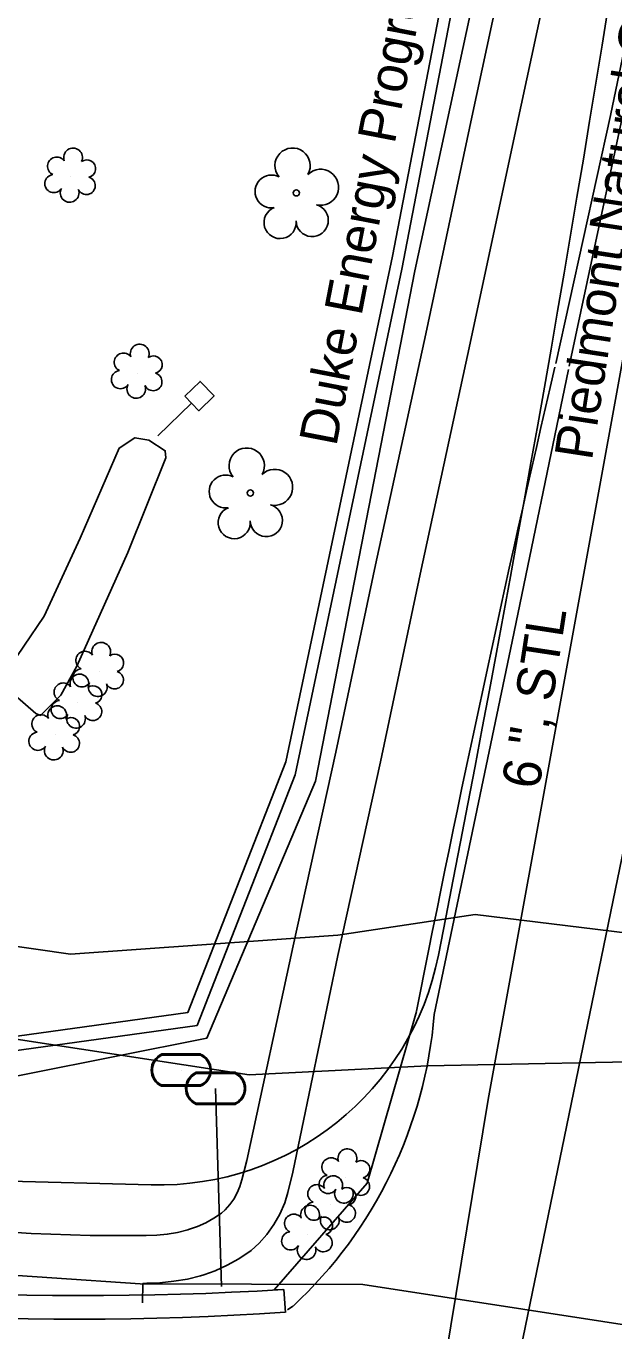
# Model space of a CAD drawing. Extents: x 1614427 to 1617186, y 896524 to 905462.
# Drawn here: x 1616565.9 to 1616627.8, y 901675.1 to 901812.5 of the extents above; entities that cross this region are included whole.
import ezdxf

# ---------------------------------------------------------------- set-up
doc = ezdxf.new("R2010")
doc.units = 0
for name, color, linetype in [('Exist Building', 7, 'Continuous'), ('Exist Right of Way Line', 7, 'Continuous'), ('Exist Roads Curbs', 7, 'Continuous'), ('Exist Roads EOP', 7, 'Continuous'), ('Exist Roads EOP Other', 7, 'Continuous'), ('Exist Roads EOT', 7, 'Continuous'), ('Exist Utilities Gas UG Line SUE LOS B', 7, 'Continuous'), ('Exist Utilities Gas UG Line SUE LOS B Text', 7, 'Continuous'), ('Exist Utilities Power UG Cable SUE LOS B', 7, 'Continuous'), ('Exist Utilities Power UG Cable SUE LOS B Text', 7, 'Continuous'), ('Exist Utilities Telephone UG Cable SUE LOS B', 7, 'Continuous'), ('Exist Utilities Telephone UG FO SUE LOS B', 7, 'Continuous'), ('Exist Utilities TV UG FO Cable SUE LOS B', 7, 'Continuous'), ('Exist Utilities Water Meter CELL', 7, 'Continuous'), ('Exist Utilities Water UG Line SUE LOS B', 7, 'Continuous'), ('Exist Vegetation Hedge Row', 7, 'Continuous'), ('Exist Vegetation Shrub CELL', 7, 'Continuous'), ('Exist Vegetation Tree CELL', 7, 'Continuous')]:
    doc.layers.add(name, color=color, linetype=linetype)

# ---------------------------------------------------------------- blocks, each defined once
blk = doc.blocks.new('EXIST UTILITIES WATER METER')
at = {"layer": 'Exist Utilities Water Meter CELL'}
blk.add_line((0, 0), (0, 0), dxfattribs=at)
for points in [[(-0.0408, 0.034), (0.0408, 0.034)], [(-0.0408, 0.0312), (0.0408, 0.0312)], [(0.0408, -0.0312), (-0.0413, -0.0312)], [(0.0408, -0.034), (-0.0413, -0.034)]]:
    blk.add_lwpolyline(points, dxfattribs=at)
for centre, radius, start, end in [((-0.0261, -0.0001), 0.0371, 113.178, 245.9794), ((-0.0259, -0.0001), 0.0347, 115.3009, 243.7824), ((0.0259, 0), 0.0371, 293.6483, 66.3084), ((0.0261, 0), 0.0345, 295.1272, 64.8728)]:
    blk.add_arc(centre, radius, start, end, dxfattribs=at)

msp = doc.modelspace()

# ---------------------------------------------------------------- linework, layer by layer
at = {"layer": 'Exist Building'}
msp.add_lwpolyline([(1616582.61, 901773.54), (1616584.21, 901775.1), (1616585.69, 901773.57), (1616584.09, 901772.01)], close=True, dxfattribs=at)
msp.add_lwpolyline([(1616579.75, 901769.36), (1616583.32, 901772.8)], dxfattribs=at)
at = {"layer": 'Exist Right of Way Line'}
msp.add_line((1616553.32, 901691.18), (1616579.08, 901690.51), dxfattribs=at)
for centre, radius, start, end in [((1613828.3, 902264.36), 2834.79, 348.81938, 354.06667), ((1616579.86, 901720.5), 30, 268.5167, 348.8194)]:
    msp.add_arc(centre, radius, start, end, dxfattribs=at)
at = {"layer": 'Exist Roads Curbs'}
msp.add_ellipse((1616573.1, 902027.68), major_axis=(332.83, 110.98), ratio=0.993612, start_param=4.203204, end_param=4.448986, dxfattribs=at)
msp.add_spline([(1616576.44, 901651.14), (1616560.36, 901651.87), (1616541.57, 901653.2), (1616514.26, 901656.47), (1616480.87, 901662.8), (1616452.55, 901670.88), (1616427.97, 901679.5)], degree=3, dxfattribs=at)
at = {"layer": 'Exist Roads EOP'}
for p, q in [((1616601.81, 901690.68), (1616606.99, 901708.78)), ((1616592.01, 901679.45), (1616601.81, 901690.68)), ((1616593.04, 901679.48), (1616592.01, 901679.45)), ((1616593.19, 901677.09), (1616593.04, 901679.48))]:
    msp.add_line(p, q, dxfattribs=at)
msp.add_lwpolyline([(1616621.64, 901776.98), (1616627.39, 901803.1), (1616632.77, 901828.92), (1616641.71, 901868.37), (1616650.08, 901907.37), (1616655.28, 901931.6)], dxfattribs=at)
for centre, major_axis, ratio, start_param, end_param in [((1618623.91, 901315), (-543.78, -2018.83), 0.982805, 4.748311, 4.78148), ((1616571.82, 902020.2), (313.25, 144.66), 0.995767, 4.092093, 4.343375)]:
    msp.add_ellipse(centre, major_axis=major_axis, ratio=ratio, start_param=start_param, end_param=end_param, dxfattribs=at)
msp.add_spline([(1616600.7, 901615.07), (1616596.49, 901640.71), (1616577.82, 901651.88), (1616577.76, 901653.58), (1616560.38, 901654.4), (1616541.66, 901655.74), (1616514.62, 901658.97), (1616481.57, 901665.46), (1616453.29, 901673.28), (1616429.01, 901681.85), (1616427.56, 901682.36), (1616413.54, 901687.44), (1616400.43, 901690.54), (1616382.85, 901691.64), (1616359.81, 901688.16), (1616349.76, 901685.26), (1616334.54, 901681.3), (1616320.23, 901678.77)], degree=3, dxfattribs=at)
at = {"layer": 'Exist Roads EOP Other'}
for points in [[(1616558.2, 901685.95), (1616566.42, 901685.4), (1616572.64, 901685.18), (1616578.48, 901685.18), (1616578.55, 901685.17), (1616579.66, 901685.21), (1616580.76, 901685.31), (1616581.84, 901685.5), (1616582.91, 901685.77), (1616583.01, 901685.8), (1616583.93, 901686.12), (1616584.81, 901686.52), (1616585.66, 901686.99), (1616586.46, 901687.53), (1616586.84, 901687.88), (1616587.33, 901688.43), (1616587.76, 901689.02), (1616588.12, 901689.66), (1616588.4, 901690.33), (1616588.62, 901691.03), (1616589.13, 901693.08), (1616594.02, 901715.68), (1616598.5, 901736.07), (1616602.69, 901755.79), (1616607.96, 901780.12), (1616612.82, 901802.9), (1616617.67, 901825.43)], [(1616578.16, 901678.11), (1616578.19, 901680.14), (1616578.61, 901680.17), (1616579.99, 901680.21), (1616581.44, 901680.36), (1616582.88, 901680.6), (1616584.26, 901680.95), (1616584.6, 901681.05), (1616585.81, 901681.48), (1616587.07, 901682.05), (1616588.28, 901682.73), (1616589.58, 901683.6), (1616590.42, 901684.37), (1616591.24, 901685.29), (1616591.99, 901686.33), (1616592.62, 901687.44), (1616593.12, 901688.62), (1616593.45, 901689.7), (1616593.99, 901691.86), (1616598.71, 901714.66), (1616603.19, 901735.05), (1616607.38, 901754.79), (1616612.65, 901779.11), (1616617.51, 901801.89), (1616622.36, 901824.42)]]:
    msp.add_lwpolyline(points, dxfattribs=at)
at = {"layer": 'Exist Roads EOT'}
msp.add_line((1616593.41, 901677.36), (1616593.99, 901677.75), dxfattribs=at)
for points in [[(1616623.04, 901776.71), (1616628.63, 901802.84), (1616634.16, 901828.59), (1616642.69, 901868.2), (1616651.43, 901907.18), (1616657.03, 901931.53)], [(1616608.85, 901708.44), (1616617.05, 901747.7), (1616622.98, 901776.36)]]:
    msp.add_lwpolyline(points, dxfattribs=at)
msp.add_ellipse((1616561.86, 901712.27), major_axis=(4.78, 46.93), ratio=0.999551, start_param=3.993091, end_param=4.732604, dxfattribs=at)
at = {"layer": 'Exist Utilities Gas UG Line SUE LOS B'}
msp.add_lwpolyline([(1616538.79, 901324.29), (1616552.84, 901386.17), (1616571.68, 901471.14), (1616584.04, 901531.54), (1616593.62, 901586.74), (1616603.9, 901635.05), (1616614.54, 901699.5), (1616631.36, 901792.12), (1616640.8, 901853.71), (1616647.39, 901906.62), (1616655.55, 901983.89), (1616661.01, 902037.25)], dxfattribs=at)
at = {"layer": 'Exist Utilities Power UG Cable SUE LOS B'}
for points in [[(1616454.2, 901982.47), (1616452.09, 901959.01), (1616448.15, 901937.94), (1616436.91, 901904.44), (1616414.57, 901852.23), (1616406.71, 901821.07), (1616409.3, 901784.96), (1616413.11, 901774.57), (1616426.11, 901752.3), (1616435.59, 901746.32), (1616447.34, 901733.78), (1616483.5, 901710.48), (1616530.04, 901703.19), (1616556.28, 901703.48), (1616583.9, 901707.29), (1616594.22, 901733.69), (1616605.43, 901786.91), (1616617.42, 901849.02), (1616627.72, 901895.28)], [(1616521.47, 901705.75), (1616529.07, 901704.56), (1616555.31, 901704.85), (1616582.92, 901708.65), (1616593.24, 901735.06), (1616604.45, 901788.28), (1616616.44, 901850.39), (1616626.74, 901896.65)], [(1616321.85, 901655.54), (1616340.38, 901656.93), (1616355.03, 901659.84), (1616371, 901660.64), (1616397.99, 901656.61), (1616411.28, 901688.81), (1616423.43, 901725.11), (1616429.1, 901738.02), (1616434.18, 901742.07), (1616436.04, 901741.86), (1616447.03, 901732.28), (1616483, 901709.43), (1616531.15, 901699.01), (1616556.38, 901700.28), (1616584.94, 901705.97), (1616596.35, 901733.02), (1616606.82, 901786.74), (1616620.07, 901848.21), (1616628.54, 901895.32)]]:
    msp.add_lwpolyline(points, dxfattribs=at)
at = {"layer": 'Exist Utilities Telephone UG Cable SUE LOS B'}
msp.add_lwpolyline([(1616586.65, 901614.7), (1616592.7, 901627.45), (1616597.67, 901647), (1616601.16, 901647.82), (1616608.45, 901646.9), (1616613.6, 901651.99), (1616633.98, 901750.98), (1616649.47, 901834.39), (1616660.58, 901920.16), (1616668.64, 902000.09), (1616671.96, 902044.94), (1616671.51, 902046.39), (1616670.53, 902047.17), (1616656.18, 902049.88), (1616655.65, 902049.04), (1616655.13, 902049.4), (1616655.43, 902048.87), (1616655.12, 902049.21)], dxfattribs=at)
at = {"layer": 'Exist Utilities Telephone UG FO SUE LOS B'}
msp.add_lwpolyline([(1616403.03, 901799.89), (1616405.04, 901786.96), (1616407.42, 901779.6), (1616413.72, 901777.14), (1616420.34, 901772.02), (1616441.69, 901749.86), (1616460.62, 901734.03), (1616479.89, 901715.6), (1616485.43, 901711.46), (1616493.52, 901710.05), (1616500.25, 901708.45), (1616507.39, 901707.17), (1616536.69, 901701.35), (1616564.86, 901705.85), (1616589.38, 901702.1), (1616608.14, 901703.05), (1616664.78, 901704.15), (1616671.11, 901705.31), (1616671.11, 901705.31), (1616675.41, 901706.02)], dxfattribs=at)
at = {"layer": 'Exist Utilities TV UG FO Cable SUE LOS B'}
msp.add_lwpolyline([(1616479.03, 901712.88), (1616493.29, 901712.8), (1616511.94, 901716.14), (1616527.71, 901721.38), (1616537.4, 901719.91), (1616551.56, 901717.55), (1616570.56, 901714.81), (1616598.71, 901716.8), (1616613.16, 901718.98), (1616640.43, 901715.64)], dxfattribs=at)
at = {"layer": 'Exist Utilities Water UG Line SUE LOS B'}
msp.add_line((1616585.85, 901700.67), (1616586.46, 901679.81), dxfattribs=at)
msp.add_lwpolyline([(1616540.7, 901682.62), (1616577.91, 901680.11), (1616601.34, 901680.02), (1616643.43, 901673.53)], dxfattribs=at)
at = {"layer": 'Exist Vegetation Hedge Row'}
msp.add_lwpolyline([(1616576.61, 901757.09), (1616571.26, 901745.11), (1616569.57, 901742.06), (1616567.41, 901739.93), (1616566.94, 901740.14), (1616563.4, 901743.21), (1616563.51, 901744.05), (1616567.81, 901750.37), (1616571.61, 901758.59), (1616575.69, 901768.08), (1616577.35, 901769.17), (1616578.81, 901768.92), (1616580.55, 901767.8), (1616580.6, 901767.04), (1616576.61, 901757.09)], dxfattribs=at)
at = {"layer": 'Exist Vegetation Shrub CELL'}
for p, q in [((1616570.62, 901796.63), (1616570.62, 901796.63)), ((1616577.63, 901775.98), (1616577.63, 901775.98)), ((1616573.58, 901744.59), (1616573.58, 901744.59)), ((1616571.29, 901741.25), (1616571.29, 901741.25)), ((1616568.95, 901737.92), (1616568.95, 901737.92)), ((1616599.48, 901691.27), (1616599.48, 901691.27)), ((1616597.99, 901688.44), (1616597.99, 901688.44)), ((1616595.55, 901685.33), (1616595.55, 901685.33))]:
    msp.add_line(p, q, dxfattribs=at)
for centre, radius, start, end in [((1616570.85, 901798.67), 0.99, 334.8391, 200.4717), ((1616569.13, 901797.75), 0.968, 35.8908, 245.4216), ((1616572.29, 901797.49), 0.929, 284.4567, 126.0861), ((1616568.82, 901795.92), 0.955, 95.1099, 327.9534), ((1616572.25, 901795.7), 0.937, 204.9913, 73.4601), ((1616570.49, 901794.94), 0.984, 151.2797, 21.387), ((1616577.86, 901778.02), 0.99, 334.8391, 200.4717), ((1616576.15, 901777.11), 0.968, 35.8908, 245.4216), ((1616579.3, 901776.85), 0.929, 284.4567, 126.0861), ((1616575.83, 901775.28), 0.955, 95.1099, 327.9534), ((1616579.27, 901775.05), 0.937, 204.9913, 73.4601), ((1616577.5, 901774.3), 0.984, 151.2797, 21.387), ((1616573.81, 901746.63), 0.99, 334.8391, 200.4717), ((1616572.1, 901745.72), 0.968, 35.8908, 245.4216), ((1616575.25, 901745.46), 0.929, 284.4567, 126.0861), ((1616571.78, 901743.89), 0.955, 95.1099, 327.9534), ((1616575.21, 901743.66), 0.937, 204.9913, 73.4601), ((1616569.81, 901742.38), 0.968, 35.8908, 245.4216), ((1616571.52, 901743.29), 0.99, 334.8391, 200.4717), ((1616572.96, 901742.12), 0.929, 284.4567, 126.0861), ((1616573.45, 901742.91), 0.984, 151.2797, 21.387), ((1616569.18, 901739.96), 0.99, 334.8391, 200.4717), ((1616569.49, 901740.55), 0.955, 95.1099, 327.9534), ((1616572.93, 901740.33), 0.937, 204.9913, 73.4601), ((1616567.47, 901739.04), 0.968, 35.8908, 245.4216), ((1616570.62, 901738.78), 0.929, 284.4567, 126.0861), ((1616571.16, 901739.57), 0.984, 151.2797, 21.387), ((1616567.15, 901737.21), 0.955, 95.1099, 327.9534), ((1616570.59, 901736.99), 0.937, 204.9913, 73.4601), ((1616568.82, 901736.23), 0.984, 151.2797, 21.387), ((1616599.71, 901693.31), 0.99, 334.8391, 200.4717), ((1616598, 901692.39), 0.968, 35.8908, 245.4216), ((1616601.15, 901692.14), 0.929, 284.4567, 126.0861), ((1616597.68, 901690.56), 0.955, 95.1099, 327.9534), ((1616598.22, 901690.48), 0.99, 334.8391, 200.4717), ((1616601.12, 901690.34), 0.937, 204.9913, 73.4601), ((1616596.51, 901689.57), 0.968, 35.8908, 245.4216), ((1616599.35, 901689.58), 0.984, 151.2797, 21.387), ((1616599.67, 901689.31), 0.929, 284.4567, 126.0861), ((1616595.78, 901687.37), 0.99, 334.8391, 200.4717), ((1616596.19, 901687.74), 0.955, 95.1099, 327.9534), ((1616599.63, 901687.51), 0.937, 204.9913, 73.4601), ((1616594.07, 901686.46), 0.968, 35.8908, 245.4216), ((1616597.22, 901686.2), 0.929, 284.4567, 126.0861), ((1616597.86, 901686.76), 0.984, 151.2797, 21.387), ((1616593.75, 901684.62), 0.955, 95.1099, 327.9534), ((1616597.19, 901684.4), 0.937, 204.9913, 73.4601), ((1616595.42, 901683.64), 0.984, 151.2797, 21.387)]:
    msp.add_arc(centre, radius, start, end, dxfattribs=at)
at = {"layer": 'Exist Vegetation Tree CELL'}
for p, q in [((1616594.34, 901794.94), (1616594.34, 901794.94)), ((1616589.51, 901763.35), (1616589.51, 901763.35))]:
    msp.add_line(p, q, dxfattribs=at)
for centre in [(1616594.34, 901794.94), (1616589.51, 901763.35)]:
    msp.add_circle(centre, 0.326, dxfattribs=at)
for centre, radius, start, end in [((1616593.95, 901797.81), 1.86, 330.1651, 219.7134), ((1616591.73, 901795.09), 1.73, 62.6636, 279.3457), ((1616596.89, 901795.53), 1.9, 257.1011, 134.1999), ((1616592.63, 901791.82), 1.69, 111.5671, 6.231), ((1616596.01, 901792.04), 1.7, 181.2822, 74.56), ((1616589.12, 901766.23), 1.86, 330.1651, 219.7134), ((1616586.9, 901763.51), 1.73, 62.6636, 279.3457), ((1616592.06, 901763.94), 1.9, 257.1011, 134.1999), ((1616587.81, 901760.23), 1.69, 111.5671, 6.231), ((1616591.18, 901760.46), 1.7, 181.2822, 74.56)]:
    msp.add_arc(centre, radius, start, end, dxfattribs=at)

# ---------------------------------------------------------------- block references
at = {"layer": 'Exist Utilities Water Meter CELL', "xscale": 50, "yscale": 50}
for p in [(1616582.23, 901702.59), (1616585.85, 901700.67)]:
    msp.add_blockref('EXIST UTILITIES WATER METER', p, dxfattribs=at)

# ---------------------------------------------------------------- texts
at = {"layer": 'Exist Utilities Gas UG Line SUE LOS B Text'}
for s, p in [('Piedmont Natural Gas Company Inc.', (1616625.44, 901766.69)), ('6 ", STL', (1616619.89, 901732.05))]:
    msp.add_text(s, height=4, rotation=81.2843, dxfattribs=at).set_placement(p)
at = {"layer": 'Exist Utilities Power UG Cable SUE LOS B Text'}
msp.add_text('Duke Energy Progress', height=4, rotation=79.0761, dxfattribs=at).set_placement((1616598.54, 901768.17))

doc.saveas('drawing.dxf')
